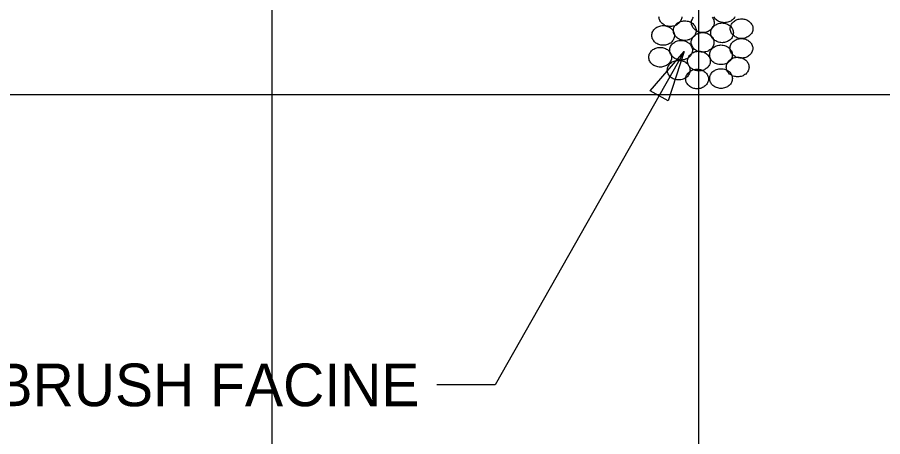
# Model space of a CAD drawing. Extents: x 1578769 to 1579225, y 724002 to 724828.
# Drawn here: x 1578851.21 to 1578861.35, y 724314.14 to 724319.06 of the extents above; entities that cross this region are included whole.
import ezdxf

# ---------------------------------------------------------------- set-up
doc = ezdxf.new("R2010")
doc.units = 0
for name, color, linetype in [('1', 7, 'Continuous'), ('Old_Level_1', 7, 'Continuous'), ('Old_Level_41', 7, 'Continuous')]:
    doc.layers.add(name, color=color, linetype=linetype)

msp = doc.modelspace()

# ---------------------------------------------------------------- linework, layer by layer
at = {"layer": '1'}
msp.add_lwpolyline([(1578859.025, 724318.657), (1578856.809, 724314.748), (1578856.124, 724314.748)], dxfattribs=at)
msp.add_lwpolyline([(1578858.625, 724318.194), (1578859.025, 724318.657), (1578858.834, 724318.076)], close=True, dxfattribs=at)
at = {"layer": 'Old_Level_1'}
for points in [[(1578858.994, 724319.064), (1578858.994, 724319.052), (1578858.992, 724319.04), (1578858.988, 724319.03), (1578858.984, 724319.019), (1578858.978, 724319.009), (1578858.971, 724318.999), (1578858.964, 724318.99), (1578858.955, 724318.982), (1578858.946, 724318.975), (1578858.936, 724318.968), (1578858.925, 724318.962), (1578858.913, 724318.958), (1578858.901, 724318.954), (1578858.888, 724318.951), (1578858.875, 724318.949), (1578858.861, 724318.949), (1578858.848, 724318.949), (1578858.835, 724318.951), (1578858.822, 724318.954), (1578858.81, 724318.958), (1578858.798, 724318.962), (1578858.787, 724318.968), (1578858.777, 724318.975), (1578858.767, 724318.982), (1578858.759, 724318.99), (1578858.751, 724318.999), (1578858.744, 724319.009), (1578858.739, 724319.019), (1578858.734, 724319.03), (1578858.731, 724319.04), (1578858.729, 724319.052), (1578858.728, 724319.064)], [(1578858.897, 724318.901), (1578858.898, 724318.912), (1578858.9, 724318.924), (1578858.903, 724318.935), (1578858.907, 724318.945), (1578858.913, 724318.955), (1578858.92, 724318.965), (1578858.927, 724318.974), (1578858.936, 724318.982), (1578858.945, 724318.99), (1578858.956, 724318.996), (1578858.967, 724319.002), (1578858.978, 724319.007), (1578858.99, 724319.011), (1578859.003, 724319.013), (1578859.016, 724319.015), (1578859.03, 724319.016), (1578859.044, 724319.015), (1578859.057, 724319.013), (1578859.069, 724319.011), (1578859.082, 724319.007), (1578859.093, 724319.002), (1578859.104, 724318.996), (1578859.114, 724318.99), (1578859.124, 724318.982), (1578859.132, 724318.974), (1578859.14, 724318.965), (1578859.147, 724318.955), (1578859.152, 724318.945), (1578859.157, 724318.935), (1578859.16, 724318.924), (1578859.162, 724318.912), (1578859.163, 724318.901), (1578859.162, 724318.889), (1578859.16, 724318.877), (1578859.157, 724318.866), (1578859.152, 724318.856), (1578859.147, 724318.846), (1578859.14, 724318.836), (1578859.132, 724318.827), (1578859.124, 724318.819), (1578859.114, 724318.812), (1578859.104, 724318.805), (1578859.093, 724318.799), (1578859.082, 724318.794), (1578859.069, 724318.791), (1578859.057, 724318.788), (1578859.044, 724318.786), (1578859.03, 724318.786), (1578859.016, 724318.786), (1578859.003, 724318.788), (1578858.99, 724318.791), (1578858.978, 724318.794), (1578858.967, 724318.799), (1578858.956, 724318.805), (1578858.945, 724318.812), (1578858.936, 724318.819), (1578858.927, 724318.827), (1578858.92, 724318.836), (1578858.913, 724318.846), (1578858.907, 724318.856), (1578858.903, 724318.866), (1578858.9, 724318.877), (1578858.898, 724318.889), (1578858.897, 724318.901), (1578858.897, 724318.901)], [(1578859.109, 724318.993), (1578859.109, 724319.005), (1578859.111, 724319.017), (1578859.115, 724319.027), (1578859.119, 724319.038), (1578859.125, 724319.048), (1578859.131, 724319.058)], [(1578859.352, 724319.058), (1578859.359, 724319.048), (1578859.364, 724319.038), (1578859.369, 724319.027), (1578859.372, 724319.017), (1578859.374, 724319.005), (1578859.374, 724318.993), (1578859.374, 724318.982), (1578859.372, 724318.97), (1578859.369, 724318.959), (1578859.364, 724318.948), (1578859.359, 724318.938), (1578859.352, 724318.929), (1578859.344, 724318.92), (1578859.336, 724318.912), (1578859.326, 724318.904), (1578859.316, 724318.898), (1578859.305, 724318.892), (1578859.293, 724318.887), (1578859.281, 724318.883), (1578859.268, 724318.88), (1578859.255, 724318.879), (1578859.242, 724318.878), (1578859.228, 724318.879), (1578859.215, 724318.88), (1578859.202, 724318.883), (1578859.19, 724318.887), (1578859.178, 724318.892), (1578859.167, 724318.898), (1578859.157, 724318.904), (1578859.148, 724318.912), (1578859.139, 724318.92), (1578859.131, 724318.929), (1578859.125, 724318.938), (1578859.119, 724318.948), (1578859.115, 724318.959), (1578859.111, 724318.97), (1578859.109, 724318.982), (1578859.109, 724318.993), (1578859.109, 724318.993)], [(1578859.617, 724319.064), (1578859.611, 724319.053), (1578859.605, 724319.044), (1578859.597, 724319.035), (1578859.588, 724319.027), (1578859.579, 724319.02), (1578859.569, 724319.013), (1578859.558, 724319.007), (1578859.546, 724319.002), (1578859.534, 724318.998), (1578859.521, 724318.996), (1578859.508, 724318.994), (1578859.495, 724318.993), (1578859.481, 724318.994), (1578859.468, 724318.996), (1578859.455, 724318.998), (1578859.443, 724319.002), (1578859.431, 724319.007), (1578859.42, 724319.013), (1578859.41, 724319.02), (1578859.401, 724319.027), (1578859.392, 724319.035), (1578859.384, 724319.044), (1578859.378, 724319.053), (1578859.372, 724319.064)], [(1578859.563, 724318.923), (1578859.563, 724318.935), (1578859.565, 724318.947), (1578859.569, 724318.957), (1578859.573, 724318.968), (1578859.579, 724318.978), (1578859.585, 724318.988), (1578859.593, 724318.997), (1578859.602, 724319.005), (1578859.611, 724319.012), (1578859.621, 724319.019), (1578859.632, 724319.025), (1578859.644, 724319.029), (1578859.656, 724319.033), (1578859.669, 724319.036), (1578859.682, 724319.038), (1578859.695, 724319.038), (1578859.709, 724319.038), (1578859.722, 724319.036), (1578859.735, 724319.033), (1578859.747, 724319.029), (1578859.759, 724319.025), (1578859.77, 724319.019), (1578859.78, 724319.012), (1578859.789, 724319.005), (1578859.798, 724318.997), (1578859.806, 724318.988), (1578859.812, 724318.978), (1578859.818, 724318.968), (1578859.822, 724318.957), (1578859.826, 724318.947), (1578859.828, 724318.935), (1578859.828, 724318.923), (1578859.828, 724318.912), (1578859.826, 724318.9), (1578859.822, 724318.889), (1578859.818, 724318.878), (1578859.812, 724318.868), (1578859.806, 724318.859), (1578859.798, 724318.85), (1578859.789, 724318.842), (1578859.78, 724318.834), (1578859.77, 724318.828), (1578859.759, 724318.822), (1578859.747, 724318.817), (1578859.735, 724318.813), (1578859.722, 724318.81), (1578859.709, 724318.809), (1578859.695, 724318.808), (1578859.682, 724318.809), (1578859.669, 724318.81), (1578859.656, 724318.813), (1578859.644, 724318.817), (1578859.632, 724318.822), (1578859.621, 724318.828), (1578859.611, 724318.834), (1578859.602, 724318.842), (1578859.593, 724318.85), (1578859.585, 724318.859), (1578859.579, 724318.868), (1578859.573, 724318.878), (1578859.569, 724318.889), (1578859.565, 724318.9), (1578859.563, 724318.912), (1578859.563, 724318.923), (1578859.563, 724318.923)], [(1578858.644, 724318.844), (1578858.645, 724318.856), (1578858.647, 724318.867), (1578858.65, 724318.878), (1578858.655, 724318.889), (1578858.66, 724318.899), (1578858.667, 724318.909), (1578858.675, 724318.917), (1578858.683, 724318.926), (1578858.692, 724318.933), (1578858.703, 724318.94), (1578858.714, 724318.945), (1578858.725, 724318.95), (1578858.738, 724318.954), (1578858.75, 724318.957), (1578858.764, 724318.959), (1578858.777, 724318.959), (1578858.791, 724318.959), (1578858.804, 724318.957), (1578858.816, 724318.954), (1578858.829, 724318.95), (1578858.84, 724318.945), (1578858.851, 724318.94), (1578858.862, 724318.933), (1578858.871, 724318.926), (1578858.879, 724318.917), (1578858.887, 724318.909), (1578858.894, 724318.899), (1578858.899, 724318.889), (1578858.904, 724318.878), (1578858.907, 724318.867), (1578858.909, 724318.856), (1578858.91, 724318.844), (1578858.909, 724318.832), (1578858.907, 724318.821), (1578858.904, 724318.81), (1578858.899, 724318.799), (1578858.894, 724318.789), (1578858.887, 724318.78), (1578858.879, 724318.771), (1578858.871, 724318.763), (1578858.862, 724318.755), (1578858.851, 724318.749), (1578858.84, 724318.743), (1578858.829, 724318.738), (1578858.816, 724318.734), (1578858.804, 724318.731), (1578858.791, 724318.73), (1578858.777, 724318.729), (1578858.764, 724318.73), (1578858.75, 724318.731), (1578858.738, 724318.734), (1578858.725, 724318.738), (1578858.714, 724318.743), (1578858.703, 724318.749), (1578858.692, 724318.755), (1578858.683, 724318.763), (1578858.675, 724318.771), (1578858.667, 724318.78), (1578858.66, 724318.789), (1578858.655, 724318.799), (1578858.65, 724318.81), (1578858.647, 724318.821), (1578858.645, 724318.832), (1578858.644, 724318.844), (1578858.644, 724318.844)], [(1578859.334, 724318.874), (1578859.335, 724318.886), (1578859.337, 724318.898), (1578859.34, 724318.909), (1578859.345, 724318.919), (1578859.35, 724318.929), (1578859.357, 724318.939), (1578859.364, 724318.948), (1578859.373, 724318.956), (1578859.383, 724318.964), (1578859.393, 724318.97), (1578859.404, 724318.976), (1578859.415, 724318.981), (1578859.427, 724318.985), (1578859.44, 724318.987), (1578859.453, 724318.989), (1578859.467, 724318.99), (1578859.481, 724318.989), (1578859.494, 724318.987), (1578859.507, 724318.985), (1578859.519, 724318.981), (1578859.53, 724318.976), (1578859.541, 724318.97), (1578859.551, 724318.964), (1578859.561, 724318.956), (1578859.57, 724318.948), (1578859.577, 724318.939), (1578859.584, 724318.929), (1578859.59, 724318.919), (1578859.594, 724318.909), (1578859.597, 724318.898), (1578859.599, 724318.886), (1578859.6, 724318.874), (1578859.599, 724318.863), (1578859.597, 724318.851), (1578859.594, 724318.84), (1578859.59, 724318.83), (1578859.584, 724318.82), (1578859.577, 724318.81), (1578859.57, 724318.801), (1578859.561, 724318.793), (1578859.551, 724318.786), (1578859.541, 724318.779), (1578859.53, 724318.773), (1578859.519, 724318.768), (1578859.507, 724318.764), (1578859.494, 724318.762), (1578859.481, 724318.76), (1578859.467, 724318.759), (1578859.453, 724318.76), (1578859.44, 724318.762), (1578859.427, 724318.764), (1578859.415, 724318.768), (1578859.404, 724318.773), (1578859.393, 724318.779), (1578859.383, 724318.786), (1578859.373, 724318.793), (1578859.364, 724318.801), (1578859.357, 724318.81), (1578859.35, 724318.82), (1578859.345, 724318.83), (1578859.34, 724318.84), (1578859.337, 724318.851), (1578859.335, 724318.863), (1578859.334, 724318.874), (1578859.334, 724318.874)], [(1578859.107, 724318.763), (1578859.107, 724318.775), (1578859.109, 724318.786), (1578859.113, 724318.797), (1578859.117, 724318.808), (1578859.123, 724318.818), (1578859.129, 724318.827), (1578859.137, 724318.836), (1578859.145, 724318.844), (1578859.155, 724318.852), (1578859.165, 724318.858), (1578859.176, 724318.864), (1578859.188, 724318.869), (1578859.2, 724318.873), (1578859.213, 724318.876), (1578859.226, 724318.877), (1578859.24, 724318.878), (1578859.253, 724318.877), (1578859.266, 724318.876), (1578859.279, 724318.873), (1578859.291, 724318.869), (1578859.303, 724318.864), (1578859.314, 724318.858), (1578859.324, 724318.852), (1578859.333, 724318.844), (1578859.342, 724318.836), (1578859.35, 724318.827), (1578859.356, 724318.818), (1578859.362, 724318.808), (1578859.366, 724318.797), (1578859.37, 724318.786), (1578859.372, 724318.775), (1578859.372, 724318.763), (1578859.372, 724318.751), (1578859.37, 724318.74), (1578859.366, 724318.729), (1578859.362, 724318.718), (1578859.356, 724318.708), (1578859.35, 724318.698), (1578859.342, 724318.689), (1578859.333, 724318.681), (1578859.324, 724318.674), (1578859.314, 724318.667), (1578859.303, 724318.661), (1578859.291, 724318.657), (1578859.279, 724318.653), (1578859.266, 724318.65), (1578859.253, 724318.648), (1578859.24, 724318.647), (1578859.226, 724318.648), (1578859.213, 724318.65), (1578859.2, 724318.653), (1578859.188, 724318.657), (1578859.176, 724318.661), (1578859.165, 724318.667), (1578859.155, 724318.674), (1578859.145, 724318.681), (1578859.137, 724318.689), (1578859.129, 724318.698), (1578859.123, 724318.708), (1578859.117, 724318.718), (1578859.113, 724318.729), (1578859.109, 724318.74), (1578859.107, 724318.751), (1578859.107, 724318.763), (1578859.107, 724318.763)], [(1578859.56, 724318.693), (1578859.561, 724318.705), (1578859.563, 724318.716), (1578859.566, 724318.727), (1578859.571, 724318.738), (1578859.576, 724318.748), (1578859.583, 724318.757), (1578859.591, 724318.766), (1578859.599, 724318.774), (1578859.609, 724318.782), (1578859.619, 724318.788), (1578859.63, 724318.794), (1578859.642, 724318.799), (1578859.654, 724318.803), (1578859.667, 724318.806), (1578859.68, 724318.807), (1578859.693, 724318.808), (1578859.707, 724318.807), (1578859.72, 724318.806), (1578859.733, 724318.803), (1578859.745, 724318.799), (1578859.757, 724318.794), (1578859.768, 724318.788), (1578859.778, 724318.782), (1578859.787, 724318.774), (1578859.796, 724318.766), (1578859.803, 724318.757), (1578859.81, 724318.748), (1578859.816, 724318.738), (1578859.82, 724318.727), (1578859.824, 724318.716), (1578859.826, 724318.705), (1578859.826, 724318.693), (1578859.826, 724318.681), (1578859.824, 724318.67), (1578859.82, 724318.658), (1578859.816, 724318.648), (1578859.81, 724318.638), (1578859.803, 724318.628), (1578859.796, 724318.619), (1578859.787, 724318.611), (1578859.778, 724318.604), (1578859.768, 724318.597), (1578859.757, 724318.591), (1578859.745, 724318.587), (1578859.733, 724318.583), (1578859.72, 724318.58), (1578859.707, 724318.578), (1578859.693, 724318.577), (1578859.68, 724318.578), (1578859.667, 724318.58), (1578859.654, 724318.583), (1578859.642, 724318.587), (1578859.63, 724318.591), (1578859.619, 724318.597), (1578859.609, 724318.604), (1578859.599, 724318.611), (1578859.591, 724318.619), (1578859.583, 724318.628), (1578859.576, 724318.638), (1578859.571, 724318.648), (1578859.566, 724318.658), (1578859.563, 724318.67), (1578859.561, 724318.681), (1578859.56, 724318.693), (1578859.56, 724318.693)], [(1578858.61, 724318.589), (1578858.61, 724318.601), (1578858.612, 724318.612), (1578858.615, 724318.623), (1578858.62, 724318.634), (1578858.625, 724318.644), (1578858.632, 724318.653), (1578858.64, 724318.662), (1578858.648, 724318.67), (1578858.658, 724318.678), (1578858.668, 724318.684), (1578858.679, 724318.69), (1578858.691, 724318.695), (1578858.703, 724318.699), (1578858.716, 724318.702), (1578858.729, 724318.703), (1578858.743, 724318.704), (1578858.756, 724318.703), (1578858.769, 724318.702), (1578858.782, 724318.699), (1578858.794, 724318.695), (1578858.806, 724318.69), (1578858.817, 724318.684), (1578858.827, 724318.678), (1578858.836, 724318.67), (1578858.845, 724318.662), (1578858.853, 724318.653), (1578858.859, 724318.644), (1578858.865, 724318.634), (1578858.869, 724318.623), (1578858.873, 724318.612), (1578858.875, 724318.601), (1578858.875, 724318.589), (1578858.875, 724318.577), (1578858.873, 724318.566), (1578858.869, 724318.555), (1578858.865, 724318.544), (1578858.859, 724318.534), (1578858.853, 724318.524), (1578858.845, 724318.516), (1578858.836, 724318.507), (1578858.827, 724318.5), (1578858.817, 724318.493), (1578858.806, 724318.488), (1578858.794, 724318.483), (1578858.782, 724318.479), (1578858.769, 724318.476), (1578858.756, 724318.474), (1578858.743, 724318.474), (1578858.729, 724318.474), (1578858.716, 724318.476), (1578858.703, 724318.479), (1578858.691, 724318.483), (1578858.679, 724318.488), (1578858.668, 724318.493), (1578858.658, 724318.5), (1578858.648, 724318.507), (1578858.64, 724318.516), (1578858.632, 724318.524), (1578858.625, 724318.534), (1578858.62, 724318.544), (1578858.615, 724318.555), (1578858.612, 724318.566), (1578858.61, 724318.577), (1578858.61, 724318.589), (1578858.61, 724318.589)], [(1578858.854, 724318.67), (1578858.855, 724318.682), (1578858.856, 724318.693), (1578858.86, 724318.704), (1578858.864, 724318.715), (1578858.87, 724318.725), (1578858.876, 724318.735), (1578858.884, 724318.744), (1578858.893, 724318.752), (1578858.902, 724318.759), (1578858.912, 724318.766), (1578858.923, 724318.772), (1578858.935, 724318.776), (1578858.947, 724318.78), (1578858.96, 724318.783), (1578858.973, 724318.785), (1578858.987, 724318.786), (1578859, 724318.785), (1578859.013, 724318.783), (1578859.026, 724318.78), (1578859.038, 724318.776), (1578859.05, 724318.772), (1578859.061, 724318.766), (1578859.071, 724318.759), (1578859.08, 724318.752), (1578859.089, 724318.744), (1578859.097, 724318.735), (1578859.103, 724318.725), (1578859.109, 724318.715), (1578859.114, 724318.704), (1578859.117, 724318.693), (1578859.119, 724318.682), (1578859.12, 724318.67), (1578859.119, 724318.658), (1578859.117, 724318.647), (1578859.114, 724318.636), (1578859.109, 724318.625), (1578859.103, 724318.615), (1578859.097, 724318.606), (1578859.089, 724318.597), (1578859.08, 724318.589), (1578859.071, 724318.581), (1578859.061, 724318.575), (1578859.05, 724318.569), (1578859.038, 724318.564), (1578859.026, 724318.56), (1578859.013, 724318.557), (1578859, 724318.556), (1578858.987, 724318.555), (1578858.973, 724318.556), (1578858.96, 724318.557), (1578858.947, 724318.56), (1578858.935, 724318.564), (1578858.923, 724318.569), (1578858.912, 724318.575), (1578858.902, 724318.581), (1578858.893, 724318.589), (1578858.884, 724318.597), (1578858.876, 724318.606), (1578858.87, 724318.615), (1578858.864, 724318.625), (1578858.86, 724318.636), (1578858.856, 724318.647), (1578858.855, 724318.658), (1578858.854, 724318.67), (1578858.854, 724318.67)], [(1578859.321, 724318.617), (1578859.322, 724318.629), (1578859.324, 724318.64), (1578859.327, 724318.651), (1578859.332, 724318.662), (1578859.337, 724318.672), (1578859.344, 724318.681), (1578859.352, 724318.69), (1578859.36, 724318.698), (1578859.37, 724318.706), (1578859.38, 724318.712), (1578859.391, 724318.718), (1578859.403, 724318.723), (1578859.415, 724318.727), (1578859.428, 724318.73), (1578859.441, 724318.731), (1578859.454, 724318.732), (1578859.468, 724318.731), (1578859.481, 724318.73), (1578859.494, 724318.727), (1578859.506, 724318.723), (1578859.518, 724318.718), (1578859.529, 724318.712), (1578859.539, 724318.706), (1578859.548, 724318.698), (1578859.557, 724318.69), (1578859.564, 724318.681), (1578859.571, 724318.672), (1578859.577, 724318.662), (1578859.581, 724318.651), (1578859.585, 724318.64), (1578859.587, 724318.629), (1578859.587, 724318.617), (1578859.587, 724318.605), (1578859.585, 724318.594), (1578859.581, 724318.582), (1578859.577, 724318.572), (1578859.571, 724318.562), (1578859.564, 724318.552), (1578859.557, 724318.544), (1578859.548, 724318.535), (1578859.539, 724318.528), (1578859.529, 724318.521), (1578859.518, 724318.516), (1578859.506, 724318.511), (1578859.494, 724318.507), (1578859.481, 724318.504), (1578859.468, 724318.502), (1578859.454, 724318.502), (1578859.441, 724318.502), (1578859.428, 724318.504), (1578859.415, 724318.507), (1578859.403, 724318.511), (1578859.391, 724318.516), (1578859.38, 724318.521), (1578859.37, 724318.528), (1578859.36, 724318.535), (1578859.352, 724318.544), (1578859.344, 724318.552), (1578859.337, 724318.562), (1578859.332, 724318.572), (1578859.327, 724318.582), (1578859.324, 724318.594), (1578859.322, 724318.605), (1578859.321, 724318.617), (1578859.321, 724318.617)], [(1578859.063, 724318.544), (1578859.064, 724318.555), (1578859.066, 724318.567), (1578859.069, 724318.578), (1578859.074, 724318.588), (1578859.079, 724318.598), (1578859.086, 724318.608), (1578859.094, 724318.617), (1578859.102, 724318.625), (1578859.112, 724318.633), (1578859.122, 724318.639), (1578859.133, 724318.645), (1578859.145, 724318.65), (1578859.157, 724318.654), (1578859.17, 724318.656), (1578859.183, 724318.658), (1578859.196, 724318.659), (1578859.21, 724318.658), (1578859.223, 724318.656), (1578859.236, 724318.654), (1578859.248, 724318.65), (1578859.26, 724318.645), (1578859.271, 724318.639), (1578859.281, 724318.633), (1578859.29, 724318.625), (1578859.299, 724318.617), (1578859.306, 724318.608), (1578859.313, 724318.598), (1578859.319, 724318.588), (1578859.323, 724318.578), (1578859.326, 724318.567), (1578859.329, 724318.555), (1578859.329, 724318.544), (1578859.329, 724318.532), (1578859.326, 724318.52), (1578859.323, 724318.509), (1578859.319, 724318.499), (1578859.313, 724318.489), (1578859.306, 724318.479), (1578859.299, 724318.47), (1578859.29, 724318.462), (1578859.281, 724318.455), (1578859.271, 724318.448), (1578859.26, 724318.442), (1578859.248, 724318.437), (1578859.236, 724318.434), (1578859.223, 724318.431), (1578859.21, 724318.429), (1578859.196, 724318.429), (1578859.183, 724318.429), (1578859.17, 724318.431), (1578859.157, 724318.434), (1578859.145, 724318.437), (1578859.133, 724318.442), (1578859.122, 724318.448), (1578859.112, 724318.455), (1578859.102, 724318.462), (1578859.094, 724318.47), (1578859.086, 724318.479), (1578859.079, 724318.489), (1578859.074, 724318.499), (1578859.069, 724318.509), (1578859.066, 724318.52), (1578859.064, 724318.532), (1578859.063, 724318.544), (1578859.063, 724318.544)], [(1578859.517, 724318.474), (1578859.518, 724318.485), (1578859.52, 724318.497), (1578859.523, 724318.508), (1578859.528, 724318.518), (1578859.533, 724318.528), (1578859.54, 724318.538), (1578859.548, 724318.547), (1578859.556, 724318.555), (1578859.565, 724318.563), (1578859.576, 724318.569), (1578859.587, 724318.575), (1578859.598, 724318.58), (1578859.611, 724318.584), (1578859.623, 724318.586), (1578859.637, 724318.588), (1578859.65, 724318.589), (1578859.664, 724318.588), (1578859.677, 724318.586), (1578859.69, 724318.584), (1578859.702, 724318.58), (1578859.713, 724318.575), (1578859.724, 724318.569), (1578859.735, 724318.563), (1578859.744, 724318.555), (1578859.753, 724318.547), (1578859.76, 724318.538), (1578859.767, 724318.528), (1578859.773, 724318.518), (1578859.777, 724318.508), (1578859.78, 724318.497), (1578859.782, 724318.485), (1578859.783, 724318.474), (1578859.782, 724318.462), (1578859.78, 724318.45), (1578859.777, 724318.439), (1578859.773, 724318.429), (1578859.767, 724318.419), (1578859.76, 724318.409), (1578859.753, 724318.4), (1578859.744, 724318.392), (1578859.735, 724318.385), (1578859.724, 724318.378), (1578859.713, 724318.372), (1578859.702, 724318.367), (1578859.69, 724318.364), (1578859.677, 724318.361), (1578859.664, 724318.359), (1578859.65, 724318.358), (1578859.637, 724318.359), (1578859.623, 724318.361), (1578859.611, 724318.364), (1578859.598, 724318.367), (1578859.587, 724318.372), (1578859.576, 724318.378), (1578859.565, 724318.385), (1578859.556, 724318.392), (1578859.548, 724318.4), (1578859.54, 724318.409), (1578859.533, 724318.419), (1578859.528, 724318.429), (1578859.523, 724318.439), (1578859.52, 724318.45), (1578859.518, 724318.462), (1578859.517, 724318.474), (1578859.517, 724318.474)], [(1578858.826, 724318.438), (1578858.827, 724318.449), (1578858.828, 724318.461), (1578858.832, 724318.472), (1578858.836, 724318.482), (1578858.842, 724318.492), (1578858.848, 724318.502), (1578858.856, 724318.511), (1578858.865, 724318.519), (1578858.874, 724318.527), (1578858.884, 724318.533), (1578858.895, 724318.539), (1578858.907, 724318.544), (1578858.919, 724318.548), (1578858.932, 724318.55), (1578858.945, 724318.552), (1578858.959, 724318.553), (1578858.972, 724318.552), (1578858.986, 724318.55), (1578858.998, 724318.548), (1578859.01, 724318.544), (1578859.022, 724318.539), (1578859.033, 724318.533), (1578859.043, 724318.527), (1578859.053, 724318.519), (1578859.061, 724318.511), (1578859.069, 724318.502), (1578859.075, 724318.492), (1578859.081, 724318.482), (1578859.086, 724318.472), (1578859.089, 724318.461), (1578859.091, 724318.449), (1578859.092, 724318.438), (1578859.091, 724318.426), (1578859.089, 724318.414), (1578859.086, 724318.403), (1578859.081, 724318.393), (1578859.075, 724318.383), (1578859.069, 724318.373), (1578859.061, 724318.364), (1578859.053, 724318.356), (1578859.043, 724318.349), (1578859.033, 724318.342), (1578859.022, 724318.336), (1578859.01, 724318.331), (1578858.998, 724318.328), (1578858.986, 724318.325), (1578858.972, 724318.323), (1578858.959, 724318.322), (1578858.945, 724318.323), (1578858.932, 724318.325), (1578858.919, 724318.328), (1578858.907, 724318.331), (1578858.895, 724318.336), (1578858.884, 724318.342), (1578858.874, 724318.349), (1578858.865, 724318.356), (1578858.856, 724318.364), (1578858.848, 724318.373), (1578858.842, 724318.383), (1578858.836, 724318.393), (1578858.832, 724318.403), (1578858.828, 724318.414), (1578858.827, 724318.426), (1578858.826, 724318.438), (1578858.826, 724318.438)], [(1578859.042, 724318.334), (1578859.042, 724318.345), (1578859.044, 724318.357), (1578859.048, 724318.368), (1578859.052, 724318.378), (1578859.058, 724318.388), (1578859.065, 724318.398), (1578859.072, 724318.407), (1578859.081, 724318.415), (1578859.09, 724318.422), (1578859.1, 724318.429), (1578859.111, 724318.435), (1578859.123, 724318.44), (1578859.135, 724318.444), (1578859.148, 724318.446), (1578859.161, 724318.448), (1578859.175, 724318.449), (1578859.188, 724318.448), (1578859.201, 724318.446), (1578859.214, 724318.444), (1578859.226, 724318.44), (1578859.238, 724318.435), (1578859.249, 724318.429), (1578859.259, 724318.422), (1578859.269, 724318.415), (1578859.277, 724318.407), (1578859.285, 724318.398), (1578859.292, 724318.388), (1578859.297, 724318.378), (1578859.302, 724318.368), (1578859.305, 724318.357), (1578859.307, 724318.345), (1578859.308, 724318.334), (1578859.307, 724318.322), (1578859.305, 724318.31), (1578859.302, 724318.299), (1578859.297, 724318.289), (1578859.292, 724318.279), (1578859.285, 724318.269), (1578859.277, 724318.26), (1578859.269, 724318.252), (1578859.259, 724318.245), (1578859.249, 724318.238), (1578859.238, 724318.232), (1578859.226, 724318.227), (1578859.214, 724318.224), (1578859.201, 724318.221), (1578859.188, 724318.219), (1578859.175, 724318.218), (1578859.161, 724318.219), (1578859.148, 724318.221), (1578859.135, 724318.224), (1578859.123, 724318.227), (1578859.111, 724318.232), (1578859.1, 724318.238), (1578859.09, 724318.245), (1578859.081, 724318.252), (1578859.072, 724318.26), (1578859.065, 724318.269), (1578859.058, 724318.279), (1578859.052, 724318.289), (1578859.048, 724318.299), (1578859.044, 724318.31), (1578859.042, 724318.322), (1578859.042, 724318.334), (1578859.042, 724318.334)], [(1578859.322, 724318.339), (1578859.323, 724318.351), (1578859.325, 724318.362), (1578859.328, 724318.373), (1578859.333, 724318.384), (1578859.338, 724318.394), (1578859.345, 724318.403), (1578859.353, 724318.412), (1578859.361, 724318.42), (1578859.37, 724318.428), (1578859.381, 724318.434), (1578859.392, 724318.44), (1578859.403, 724318.445), (1578859.416, 724318.449), (1578859.428, 724318.452), (1578859.442, 724318.453), (1578859.455, 724318.454), (1578859.469, 724318.453), (1578859.482, 724318.452), (1578859.494, 724318.449), (1578859.507, 724318.445), (1578859.518, 724318.44), (1578859.529, 724318.434), (1578859.54, 724318.428), (1578859.549, 724318.42), (1578859.558, 724318.412), (1578859.565, 724318.403), (1578859.572, 724318.394), (1578859.578, 724318.384), (1578859.582, 724318.373), (1578859.585, 724318.362), (1578859.587, 724318.351), (1578859.588, 724318.339), (1578859.587, 724318.327), (1578859.585, 724318.316), (1578859.582, 724318.305), (1578859.578, 724318.294), (1578859.572, 724318.284), (1578859.565, 724318.274), (1578859.558, 724318.265), (1578859.549, 724318.257), (1578859.54, 724318.25), (1578859.529, 724318.243), (1578859.518, 724318.237), (1578859.507, 724318.233), (1578859.494, 724318.229), (1578859.482, 724318.226), (1578859.469, 724318.224), (1578859.455, 724318.223), (1578859.442, 724318.224), (1578859.428, 724318.226), (1578859.416, 724318.229), (1578859.403, 724318.233), (1578859.392, 724318.237), (1578859.381, 724318.243), (1578859.37, 724318.25), (1578859.361, 724318.257), (1578859.353, 724318.265), (1578859.345, 724318.274), (1578859.338, 724318.284), (1578859.333, 724318.294), (1578859.328, 724318.305), (1578859.325, 724318.316), (1578859.323, 724318.327), (1578859.322, 724318.339), (1578859.322, 724318.339)]]:
    msp.add_lwpolyline(points, dxfattribs=at)
at = {"layer": 'Old_Level_41'}
for p, q in [((1578854.194, 724333.15), (1578854.194, 724303.15)), ((1578859.194, 724303.15), (1578859.194, 724333.15))]:
    msp.add_line(p, q, dxfattribs=at)
msp.add_lwpolyline([(1578824.194, 724318.15), (1578924.194, 724318.15)], dxfattribs=at)

# ---------------------------------------------------------------- texts
at = {"layer": '1'}
msp.add_text('LIVE BRUSH FACINE', height=0.5, dxfattribs=at).set_placement((1578849.308, 724314.499))

doc.saveas('drawing.dxf')
